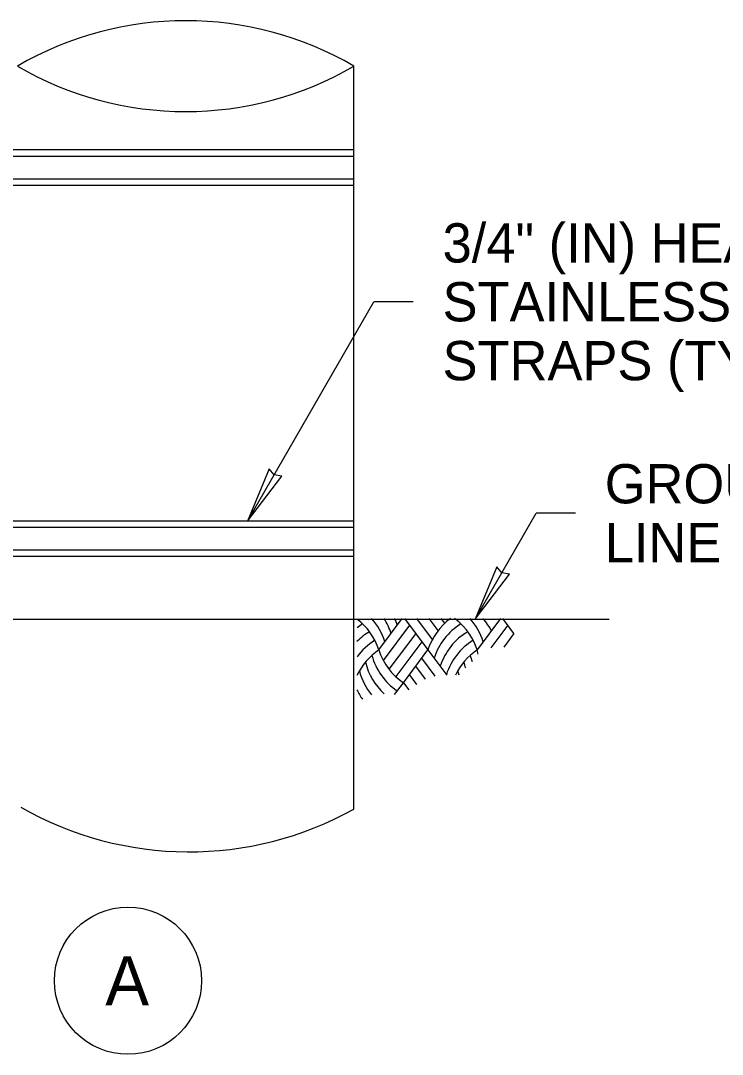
# Model space of a CAD drawing. Extents: x 99862 to 103680, y 99470 to 102076.
# Drawn here: x 101470.7 to 101756.9, y 101133.3 to 101554.8 of the extents above; entities that cross this region are included whole.
import ezdxf

# ---------------------------------------------------------------- set-up
doc = ezdxf.new("R2010")
doc.units = 0
for name, color, linetype in [('Level 10', 7, 'Continuous'), ('Level 12', 7, 'Continuous'), ('Level 14', 7, 'Continuous'), ('Level 15', 7, 'Continuous'), ('Level 20', 7, 'Continuous')]:
    doc.layers.add(name, color=color, linetype=linetype)

msp = doc.modelspace()

# ---------------------------------------------------------------- linework, layer by layer
at = {"layer": 'Level 10'}
for p, q in [((101606.65, 101310.79), (101606.65, 101536.23)), ((101606.65, 101233.33), (101606.65, 101310.79))]:
    msp.add_line(p, q, dxfattribs=at)
for centre, radius, start, end in [((101538, 101418.4), 136.37, 59.7766, 120.2234), ((101538, 101654.07), 136.37, 239.7766, 300.2234), ((101539.37, 101354.41), 138.51, 240.2717, 299.0618)]:
    msp.add_arc(centre, radius, start, end, dxfattribs=at)
at = {"layer": 'Level 12'}
for p, q in [((101247.47, 101310.82), (101710.79, 101310.82)), ((101616.81, 101298.22), (101626.39, 101311)), ((101629.33, 101308.25), (101618.61, 101293.95)), ((101627.27, 101311), (101636.85, 101298.22)), ((101638.66, 101302.5), (101632.28, 101311)), ((101640.98, 101306.08), (101637.29, 101311)), ((101643.73, 101309.1), (101642.3, 101311)), ((101666.48, 101311), (101656.9, 101298.22)), ((101669.43, 101308.25), (101662.53, 101299.05)), ((101671.89, 101304.96), (101667.36, 101311)), ((101631.84, 101304.91), (101620.93, 101290.37)), ((101671.93, 101304.91), (101667.78, 101299.37)), ((101634.35, 101301.57), (101623.69, 101287.35)), ((101626.83, 101284.86), (101636.85, 101298.22)), ((101636.85, 101298.22), (101644.59, 101287.91)), ((101635.8, 101286.26), (101631.84, 101291.54)), ((101639.83, 101287.57), (101634.35, 101294.88)), ((101632.35, 101284.18), (101629.33, 101288.2)), ((101623.21, 101280.03), (101626.83, 101284.86)), ((101626.83, 101284.86), (101628.98, 101281.99))]:
    msp.add_line(p, q, dxfattribs=at)
for centre, start, end in [((101592.63, 101290.54), 17.6434, 53.0142), ((101623.44, 101287.2), 121.4535, 127.79), ((101595.14, 101293.88), 17.6434, 42.4672), ((101597.65, 101297.22), 17.6434, 32.9186), ((101600.15, 101300.56), 17.6434, 24.3133), ((101661.02, 101290.54), 126.2068, 162.3566), ((101663.53, 101287.2), 121.4535, 162.3566), ((101632.73, 101290.54), 13.7219, 53.7932), ((101635.23, 101293.88), 17.6434, 42.4672), ((101640.56, 101293.88), 28.7646, 42.4672), ((101625.94, 101283.85), 120.6979, 135.362), ((101666.03, 101283.85), 120.6979, 162.3566), ((101628.45, 101280.51), 121.5126, 144.1302), ((101668.54, 101280.51), 121.5126, 162.3566), ((101630.95, 101277.17), 123.9036, 155.387), ((101638.47, 101302.57), 194.9887, 236.0964), ((101640.98, 101305.91), 197.6434, 236.0964), ((101671.05, 101277.17), 123.9036, 154.8033), ((101678.56, 101302.57), 194.9887, 200.8182), ((101635.97, 101299.23), 193.6801, 228.0124), ((101676.06, 101299.23), 193.6801, 199.2287), ((101633.46, 101295.89), 194.2287, 219.2182), ((101673.55, 101295.89), 194.2287, 198.026), ((101630.95, 101292.55), 204.613, 214.7711)]:
    msp.add_arc(centre, 25.36, start, end, dxfattribs=at)
at = {"layer": 'Level 14'}
for p, q in [((101606.65, 101502.07), (101387.01, 101502.07)), ((101606.65, 101499.46), (101410.49, 101499.46)), ((101606.65, 101490.17), (101410.86, 101490.17)), ((101606.65, 101487.56), (101387.01, 101487.56)), ((101606.65, 101350.77), (101387.01, 101350.77)), ((101606.65, 101348.16), (101410.49, 101348.16)), ((101606.65, 101338.86), (101410.86, 101338.86)), ((101606.65, 101336.25), (101387.01, 101336.25))]:
    msp.add_line(p, q, dxfattribs=at)
at = {"layer": 'Level 15'}
for p, q in [((101563.19, 101350.77), (101614.81, 101440.17)), ((101630.81, 101440.17), (101614.81, 101440.17)), ((101656.07, 101310.82), (101680.98, 101353.97)), ((101696.98, 101353.97), (101680.98, 101353.97))]:
    msp.add_line(p, q, dxfattribs=at)
for points in [[(101563.19, 101350.77), (101577.19, 101369.04), (101574.08, 101369.62), (101572.02, 101372.03)], [(101656.07, 101310.82), (101670.07, 101329.09), (101666.95, 101329.67), (101664.9, 101332.08)]]:
    msp.add_lwpolyline(points, close=True, dxfattribs=at)
at = {"layer": 'Level 20'}
msp.add_circle((101514.46, 101163.34), 30, dxfattribs=at)

# ---------------------------------------------------------------- texts
for s, height, p in [('3/4" (IN) HEAVY DUTY', 16, (101642.81, 101456.17)), ('STAINLESS STEEL', 16, (101642.81, 101432.17)), ('STRAPS (TYP.)', 16, (101642.81, 101408.17)), ('A', 20, (101505.21, 101153.34))]:
    msp.add_text(s, height=height, dxfattribs=at).set_placement(p)
for s, p in [('GROUND', (101708.98, 101357.97)), ('LINE', (101708.98, 101333.97))]:
    msp.add_text(s, height=16, rotation=360, dxfattribs=at).set_placement(p)

doc.saveas('drawing.dxf')
